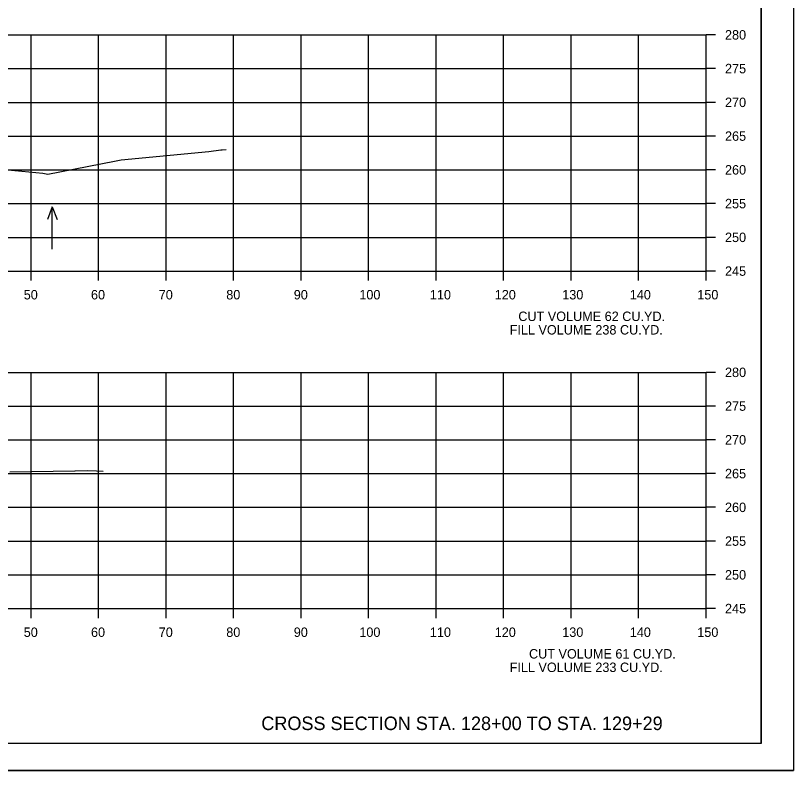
# Model space of a CAD drawing. Extents: x 1103485 to 1107180, y 2010593 to 2011873.
# Drawn here: x 1107064.9 to 1107180.1, y 2011019.5 to 2011131.3 of the extents above; entities that cross this region are included whole.
import ezdxf

# ---------------------------------------------------------------- set-up
doc = ezdxf.new("R2010")
doc.units = 0
for name, color, linetype in [('R_Axis', 7, 'Continuous'), ('R_Axis Annot', 7, 'Continuous'), ('R_Border', 7, 'Continuous'), ('R_Draft', 7, 'Continuous'), ('R_Exist Surface', 7, 'Continuous'), ('R_Grid', 7, 'Continuous'), ('R_No Plot', 7, 'Continuous'), ('R_Water Annot', 7, 'Continuous')]:
    doc.layers.add(name, color=color, linetype=linetype)

msp = doc.modelspace()

# ---------------------------------------------------------------- linework, layer by layer
at = {"layer": 'R_Axis'}
for p, q in [((1107167.18, 2011093.49), (1107167.18, 2011128.49)), ((1107168.58, 2011128.49), (1107167.18, 2011128.49)), ((1107168.58, 2011123.49), (1107167.18, 2011123.49)), ((1107168.58, 2011118.49), (1107167.18, 2011118.49)), ((1107168.58, 2011113.49), (1107167.18, 2011113.49)), ((1107168.58, 2011108.49), (1107167.18, 2011108.49)), ((1107168.58, 2011103.49), (1107167.18, 2011103.49)), ((1107168.58, 2011098.49), (1107167.18, 2011098.49)), ((1106867.18, 2011093.49), (1107167.18, 2011093.49)), ((1107067.18, 2011092.09), (1107067.18, 2011093.49)), ((1107077.18, 2011092.09), (1107077.18, 2011093.49)), ((1107087.18, 2011092.09), (1107087.18, 2011093.49)), ((1107097.18, 2011092.09), (1107097.18, 2011093.49)), ((1107107.18, 2011092.09), (1107107.18, 2011093.49)), ((1107117.18, 2011092.09), (1107117.18, 2011093.49)), ((1107127.18, 2011092.09), (1107127.18, 2011093.49)), ((1107137.18, 2011092.09), (1107137.18, 2011093.49)), ((1107147.18, 2011092.09), (1107147.18, 2011093.49)), ((1107157.18, 2011092.09), (1107157.18, 2011093.49)), ((1107167.18, 2011092.09), (1107167.18, 2011093.49)), ((1107168.58, 2011093.49), (1107167.18, 2011093.49)), ((1107167.18, 2011043.49), (1107167.18, 2011078.49)), ((1107168.58, 2011078.49), (1107167.18, 2011078.49)), ((1107168.58, 2011073.49), (1107167.18, 2011073.49)), ((1107168.58, 2011068.49), (1107167.18, 2011068.49)), ((1107168.58, 2011063.49), (1107167.18, 2011063.49)), ((1107168.58, 2011058.49), (1107167.18, 2011058.49)), ((1107168.58, 2011053.49), (1107167.18, 2011053.49)), ((1107168.58, 2011048.49), (1107167.18, 2011048.49)), ((1106867.18, 2011043.49), (1107167.18, 2011043.49)), ((1107067.18, 2011042.09), (1107067.18, 2011043.49)), ((1107077.18, 2011042.09), (1107077.18, 2011043.49)), ((1107087.18, 2011042.09), (1107087.18, 2011043.49)), ((1107097.18, 2011042.09), (1107097.18, 2011043.49)), ((1107107.18, 2011042.09), (1107107.18, 2011043.49)), ((1107117.18, 2011042.09), (1107117.18, 2011043.49)), ((1107127.18, 2011042.09), (1107127.18, 2011043.49)), ((1107137.18, 2011042.09), (1107137.18, 2011043.49)), ((1107147.18, 2011042.09), (1107147.18, 2011043.49)), ((1107157.18, 2011042.09), (1107157.18, 2011043.49)), ((1107167.18, 2011042.09), (1107167.18, 2011043.49)), ((1107168.58, 2011043.49), (1107167.18, 2011043.49))]:
    msp.add_line(p, q, dxfattribs=at)
at = {"layer": 'R_Border'}
for q in [(1107175.36, 2011228.95), (1106859.18, 2011023.49)]:
    msp.add_line((1107175.36, 2011023.49), q, dxfattribs=at)
at = {"layer": 'R_Exist Surface'}
for points in [[(1107049.2, 2011109.86), (1107068.93, 2011108), (1107069.67, 2011107.84), (1107079.53, 2011109.78), (1107080.52, 2011109.99), (1107093.5, 2011111.23), (1107095.32, 2011111.44), (1107095.34, 2011111.43), (1107095.48, 2011111.45), (1107096.07, 2011111.52)], [(1107064.02, 2011063.76), (1107073.65, 2011063.89), (1107073.74, 2011063.9), (1107075.53, 2011063.94), (1107076.88, 2011063.89), (1107077.88, 2011063.85)]]:
    msp.add_lwpolyline(points, dxfattribs=at)
at = {"layer": 'R_Grid'}
for p, q in [((1106867.18, 2011128.49), (1107167.18, 2011128.49)), ((1107067.18, 2011093.49), (1107067.18, 2011128.49)), ((1107077.18, 2011093.49), (1107077.18, 2011128.49)), ((1107087.18, 2011093.49), (1107087.18, 2011128.49)), ((1107097.18, 2011093.49), (1107097.18, 2011128.49)), ((1107107.18, 2011093.49), (1107107.18, 2011128.49)), ((1107117.18, 2011093.49), (1107117.18, 2011128.49)), ((1107127.18, 2011093.49), (1107127.18, 2011128.49)), ((1107137.18, 2011093.49), (1107137.18, 2011128.49)), ((1107147.18, 2011093.49), (1107147.18, 2011128.49)), ((1107157.18, 2011093.49), (1107157.18, 2011128.49)), ((1107167.18, 2011093.49), (1107167.18, 2011128.49)), ((1106867.18, 2011123.49), (1107167.18, 2011123.49)), ((1106867.18, 2011118.49), (1107167.18, 2011118.49)), ((1106867.18, 2011113.49), (1107167.18, 2011113.49)), ((1106867.18, 2011108.49), (1107167.18, 2011108.49)), ((1106867.18, 2011103.49), (1107167.18, 2011103.49)), ((1106867.18, 2011098.49), (1107167.18, 2011098.49)), ((1106867.18, 2011093.49), (1107167.18, 2011093.49)), ((1106867.18, 2011078.49), (1107167.18, 2011078.49)), ((1107067.18, 2011043.49), (1107067.18, 2011078.49)), ((1107077.18, 2011043.49), (1107077.18, 2011078.49)), ((1107087.18, 2011043.49), (1107087.18, 2011078.49)), ((1107097.18, 2011043.49), (1107097.18, 2011078.49)), ((1107107.18, 2011043.49), (1107107.18, 2011078.49)), ((1107117.18, 2011043.49), (1107117.18, 2011078.49)), ((1107127.18, 2011043.49), (1107127.18, 2011078.49)), ((1107137.18, 2011043.49), (1107137.18, 2011078.49)), ((1107147.18, 2011043.49), (1107147.18, 2011078.49)), ((1107157.18, 2011043.49), (1107157.18, 2011078.49)), ((1107167.18, 2011043.49), (1107167.18, 2011078.49)), ((1106867.18, 2011073.49), (1107167.18, 2011073.49)), ((1106867.18, 2011068.49), (1107167.18, 2011068.49)), ((1106867.18, 2011063.49), (1107167.18, 2011063.49)), ((1106867.18, 2011058.49), (1107167.18, 2011058.49)), ((1106867.18, 2011053.49), (1107167.18, 2011053.49)), ((1106867.18, 2011048.49), (1107167.18, 2011048.49)), ((1106867.18, 2011043.49), (1107167.18, 2011043.49))]:
    msp.add_line(p, q, dxfattribs=at)
at = {"layer": 'R_No Plot'}
msp.add_line((1106846.78, 2011019.51), (1107180.12, 2011019.51), dxfattribs=at)
for points in [[(1106846.78, 2011232.85), (1107180.12, 2011232.85), (1107180.12, 2011019.51), (1106846.78, 2011019.51)], [(1107093.1, 2011228.95), (1107093.1, 2011219.07), (1107128.84, 2011219.07), (1107128.84, 2011216.15), (1107152.04, 2011216.15), (1107152.04, 2011191.82), (1107175.36, 2011191.82), (1107175.36, 2011023.49), (1106859.18, 2011023.49), (1106859.18, 2011228.95)]]:
    msp.add_lwpolyline(points, close=True, dxfattribs=at)
at = {"layer": 'R_Water Annot'}
for p, q in [((1107070.33, 2011103.03), (1107069.63, 2011101.11)), ((1107070.33, 2011096.75), (1107070.33, 2011103.03)), ((1107070.33, 2011103.03), (1107071.03, 2011101.11))]:
    msp.add_line(p, q, dxfattribs=at)

# ---------------------------------------------------------------- texts
at = {"layer": 'R_Axis Annot'}
for s, p in [('280', (1107169.98, 2011127.79)), ('275', (1107169.98, 2011122.79)), ('270', (1107169.98, 2011117.79)), ('265', (1107169.98, 2011112.79)), ('260', (1107169.98, 2011107.79)), ('255', (1107169.98, 2011102.79)), ('250', (1107169.98, 2011097.79)), ('245', (1107169.98, 2011092.79)), ('50', (1107066.1, 2011089.29)), ('60', (1107076.06, 2011089.29)), ('70', (1107086.1, 2011089.29)), ('80', (1107096.1, 2011089.29)), ('90', (1107106.1, 2011089.29)), ('100', (1107115.81, 2011089.29)), ('110', (1107126.26, 2011089.29)), ('120', (1107135.87, 2011089.29)), ('130', (1107145.87, 2011089.29)), ('140', (1107155.87, 2011089.29)), ('150', (1107165.87, 2011089.29)), ('CUT VOLUME 62 CU.YD.', (1107139.36, 2011086.09)), ('FILL VOLUME 238 CU.YD.', (1107138.08, 2011084.09)), ('280', (1107169.98, 2011077.79)), ('275', (1107169.98, 2011072.79)), ('270', (1107169.98, 2011067.79)), ('265', (1107169.98, 2011062.79)), ('260', (1107169.98, 2011057.79)), ('255', (1107169.98, 2011052.79)), ('250', (1107169.98, 2011047.79)), ('245', (1107169.98, 2011042.79)), ('50', (1107066.1, 2011039.29)), ('60', (1107076.06, 2011039.29)), ('70', (1107086.1, 2011039.29)), ('80', (1107096.1, 2011039.29)), ('90', (1107106.1, 2011039.29)), ('100', (1107115.81, 2011039.29)), ('110', (1107126.26, 2011039.29)), ('120', (1107135.87, 2011039.29)), ('130', (1107145.87, 2011039.29)), ('140', (1107155.87, 2011039.29)), ('150', (1107165.87, 2011039.29)), ('CUT VOLUME 61 CU.YD.', (1107140.95, 2011036.09)), ('FILL VOLUME 233 CU.YD.', (1107138.08, 2011034.09))]:
    msp.add_text(s, height=1.4, dxfattribs=at).set_placement(p)
at = {"layer": 'R_Draft'}
msp.add_text('CROSS SECTION STA. 128+00 TO STA. 129+29', height=2, dxfattribs=at).set_placement((1107101.29, 2011025.49))

doc.saveas('drawing.dxf')
